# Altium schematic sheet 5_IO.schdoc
size 302 x 215 mm
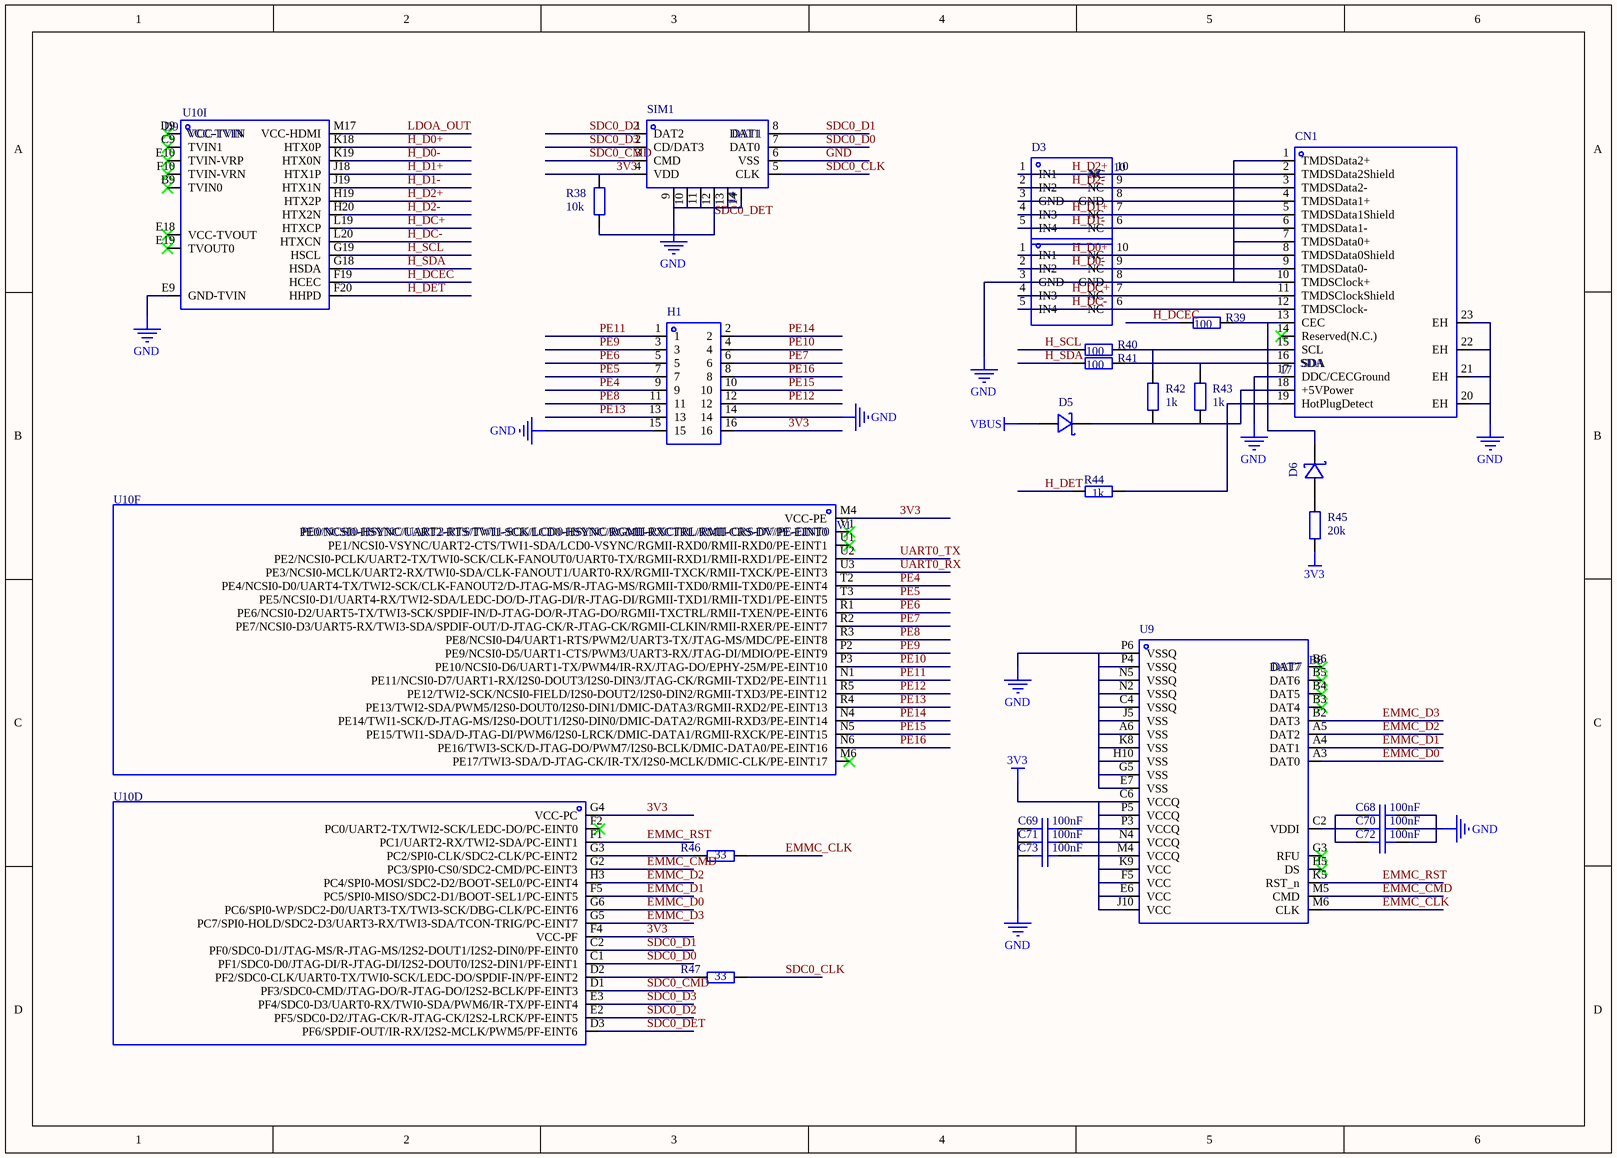
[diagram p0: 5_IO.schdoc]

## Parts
C68  value 100nF
C69  value 100nF
C70  value 100nF
C71  value 100nF
C72  value 100nF
C73  value 100nF
CN1  NUMBER: 17  NAME: SDA  [HDMI-SMD_HD219F-3D05200]
D3  NAME: NC  NUMBER: 10  [SLP2510P8_L2.5-W1.0-P0.50-BL]
D4  (no value)  [SLP2510P8_L2.5-W1.0-P0.50-BL]
D5  (no value)  [SOD-323_L1.8-W1.3-LS2.5-RD]
D6  (no value)  [SOD-323_L1.8-W1.3-LS2.5-RD]
H1  (no value)  [HDR-SMD_16P-P2.54-V-M-R2-C8-S7.4]
R38  value 10k
R39  value 100
R40  value 100
R41  value 100
R42  value 1k
R43  value 1k
R44  value 1k
R45  value 20k
R46  value 33
R47  value 33
SIM1  NAME: DAT1  NUMBER: 14  [SIM-SMD_8P-1040310811]
U9  NAME: DAT7  NUMBER: B6  [FBGA-153_L13.0-W11.5]
U10  (no value)  [ALLWINNER D1]  (parts D,F,I of 10)

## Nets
3V3: C69.1 C71.1 C73.1 H1.16 R38.1 R45.1 SIM1.4(VDD) U9.C6(VCCQ) U9.E6(VCC) U9.F5(VCC) U9.J10(VCC) U9.K9(VCC) U9.M4(VCCQ) U9.N4(VCCQ) U9.P3(VCCQ) U9.P5(VCCQ) U10.F4(VCC-PF) U10.G4(VCC-PC) U10.M4(VCC-PE)
GND: C68.1 C69.2 C70.1 C71.2 C72.1 C73.2 CN1.1(TMDSData2+) CN1.4(TMDSData1+) CN1.7(TMDSData0+) CN1.10(TMDSClock+) CN1.17(DDC/CECGround) CN1.20(EH) CN1.21(EH) CN1.22(EH) CN1.23(EH) D3.3(GND) D3.8(GND) D4.3(GND) D4.8(GND) H1.14 H1.15 SIM1.6(VSS) SIM1.9 SIM1.10 SIM1.11 SIM1.13 SIM1.14 U9.A6(VSS) U9.C4(VSSQ) U9.E7(VSS) U9.G5(VSS) U9.H10(VSS) U9.J5(VSS) U9.K8(VSS) U9.N2(VSSQ) U9.N5(VSSQ) U9.P4(VSSQ) U9.P6(VSSQ) U10.E9(GND-TVIN)
VBUS: D5.2(A)
EMMC_CLK: R46.2 U9.M6(CLK)
EMMC_CMD: U9.M5(CMD) U10.G2(PC3/SPI0-CS0/SDC2-CMD/PC-EINT3)
EMMC_D0: U9.A3(DAT0) U10.G6(PC6/SPI0-WP/SDC2-D0/UART3-TX/TWI3-SCK/DBG-CLK/PC-EINT6)
EMMC_D1: U9.A4(DAT1) U10.F5(PC5/SPI0-MISO/SDC2-D1/BOOT-SEL1/PC-EINT5)
EMMC_D2: U9.A5(DAT2) U10.H3(PC4/SPI0-MOSI/SDC2-D2/BOOT-SEL0/PC-EINT4)
EMMC_D3: U9.B2(DAT3) U10.G5(PC7/SPI0-HOLD/SDC2-D3/UART3-RX/TWI3-SDA/TCON-TRIG/PC-EINT7)
EMMC_RST: U9.K5(RST_n) U10.F1(PC1/UART2-RX/TWI2-SDA/PC-EINT1)
H_D0+: CN1.8(TMDSData0Shield) D4.1(IN1) D4.10(NC) U10.K18(HTX0P)
H_D0-: CN1.9(TMDSData0-) D4.2(IN2) D4.9(NC) U10.K19(HTX0N)
H_D1+: CN1.5(TMDSData1Shield) D3.4(IN3) D3.7(NC) U10.J18(HTX1P)
H_D1-: CN1.6(TMDSData1-) D3.5(IN4) D3.6(NC) U10.J19(HTX1N)
H_D2+: CN1.2(TMDSData2Shield) D3.1(IN1) D3.10(NC) U10.H19(HTX2P)
H_D2-: CN1.3(TMDSData2-) D3.2(IN2) D3.9(NC) U10.H20(HTX2N)
H_DC+: CN1.11(TMDSClockShield) D4.4(IN3) D4.7(NC) U10.L19(HTXCP)
H_DC-: CN1.12(TMDSClock-) D4.5(IN4) D4.6(NC) U10.L20(HTXCN)
H_DCEC: R39.2 U10.F19(HCEC)
H_DET: R44.2 U10.F20(HHPD)
H_SCL: R40.2 U10.G19(HSCL)
H_SDA: R41.2 U10.G18(HSDA)
LDOA_OUT: U10.M17(VCC-HDMI)
PE4: H1.9 U10.T2(PE4/NCSI0-D0/UART4-TX/TWI2-SCK/CLK-FANOUT2/D-JTAG-MS/R-JTAG-MS/RGMII-TXD0/RMII-TXD0/PE-EINT4)
PE5: H1.7 U10.T3(PE5/NCSI0-D1/UART4-RX/TWI2-SDA/LEDC-DO/D-JTAG-DI/R-JTAG-DI/RGMII-TXD1/RMII-TXD1/PE-EINT5)
PE6: H1.5 U10.R1(PE6/NCSI0-D2/UART5-TX/TWI3-SCK/SPDIF-IN/D-JTAG-DO/R-JTAG-DO/RGMII-TXCTRL/RMII-TXEN/PE-EINT6)
PE7: H1.6 U10.R2(PE7/NCSI0-D3/UART5-RX/TWI3-SDA/SPDIF-OUT/D-JTAG-CK/R-JTAG-CK/RGMII-CLKIN/RMII-RXER/PE-EINT7)
PE8: H1.11 U10.R3(PE8/NCSI0-D4/UART1-RTS/PWM2/UART3-TX/JTAG-MS/MDC/PE-EINT8)
PE9: H1.3 U10.P2(PE9/NCSI0-D5/UART1-CTS/PWM3/UART3-RX/JTAG-DI/MDIO/PE-EINT9)
PE10: H1.4 U10.P3(PE10/NCSI0-D6/UART1-TX/PWM4/IR-RX/JTAG-DO/EPHY-25M/PE-EINT10)
PE11: H1.1 U10.N1(PE11/NCSI0-D7/UART1-RX/I2S0-DOUT3/I2S0-DIN3/JTAG-CK/RGMII-TXD2/PE-EINT11)
PE12: H1.12 U10.R5(PE12/TWI2-SCK/NCSI0-FIELD/I2S0-DOUT2/I2S0-DIN2/RGMII-TXD3/PE-EINT12)
PE13: H1.13 U10.R4(PE13/TWI2-SDA/PWM5/I2S0-DOUT0/I2S0-DIN1/DMIC-DATA3/RGMII-RXD2/PE-EINT13)
PE14: H1.2 U10.N4(PE14/TWI1-SCK/D-JTAG-MS/I2S0-DOUT1/I2S0-DIN0/DMIC-DATA2/RGMII-RXD3/PE-EINT14)
PE15: H1.10 U10.N5(PE15/TWI1-SDA/D-JTAG-DI/PWM6/I2S0-LRCK/DMIC-DATA1/RGMII-RXCK/PE-EINT15)
PE16: H1.8 U10.N6(PE16/TWI3-SCK/D-JTAG-DO/PWM7/I2S0-BCLK/DMIC-DATA0/PE-EINT16)
SDC0_CLK: R47.2 SIM1.5(CLK)
SDC0_CMD: SIM1.3(CMD) U10.D1(PF3/SDC0-CMD/JTAG-DO/R-JTAG-DO/I2S2-BCLK/PF-EINT3)
SDC0_D0: SIM1.7(DAT0) U10.C1(PF1/SDC0-D0/JTAG-DI/R-JTAG-DI/I2S2-DOUT0/I2S2-DIN1/PF-EINT1)
SDC0_D1: SIM1.8(DAT1) U10.C2(PF0/SDC0-D1/JTAG-MS/R-JTAG-MS/I2S2-DOUT1/I2S2-DIN0/PF-EINT0)
SDC0_D2: SIM1.1(DAT2) U10.E2(PF5/SDC0-D2/JTAG-CK/R-JTAG-CK/I2S2-LRCK/PF-EINT5)
SDC0_D3: SIM1.2(CD/DAT3) U10.E3(PF4/SDC0-D3/UART0-RX/TWI0-SDA/PWM6/IR-TX/PF-EINT4)
SDC0_DET: R38.2 SIM1.12 U10.D3(PF6/SPDIF-OUT/IR-RX/I2S2-MCLK/PWM5/PF-EINT6)
UART0_RX: U10.U3(PE3/NCSI0-MCLK/UART2-RX/TWI0-SDA/CLK-FANOUT1/UART0-RX/RGMII-TXCK/RMII-TXCK/PE-EINT3)
UART0_TX: U10.U2(PE2/NCSI0-PCLK/UART2-TX/TWI0-SCK/CLK-FANOUT0/UART0-TX/RGMII-RXD1/RMII-RXD1/PE-EINT2)
NetC68_2: C68.2 C70.2 C72.2 U9.C2(VDDI)
NetCN1_13: CN1.13(CEC) D6.1(C) R39.1
NetCN1_15: CN1.15(SCL) R40.1 R42.2
NetCN1_16: CN1.16(SDA) R41.1 R43.2
NetCN1_18: CN1.18(+5VPower) D5.1(C) R42.1 R43.1
NetCN1_19: CN1.19(HotPlugDetect) R44.1
NetD6_2: D6.2(A) R45.2
NetR46_1: R46.1 U10.G3(PC2/SPI0-CLK/SDC2-CLK/PC-EINT2)
NetR47_1: R47.1 U10.D2(PF2/SDC0-CLK/UART0-TX/TWI0-SCK/LEDC-DO/SPDIF-IN/PF-EINT2)

Not connected (* = marked no-connect by the designer): CN1 14(Reserved(N.C.))*; U9 B3(DAT4)* B4(DAT5)* B5(DAT6)* B6(DAT7)* G3(RFU)* H5(DS)*; U10 B9(TVIN0)* C9(TVIN1)* D9(VCC-TVIN)* E10(TVIN-VRP)* E18(VCC-TVOUT)* E19(TVOUT0)* F2(PC0/UART2-TX/TWI2-SCK/LEDC-DO/PC-EINT0)* F10(TVIN-VRN)* M6(PE17/TWI3-SDA/D-JTAG-CK/IR-TX/I2S0-MCLK/DMIC-CLK/PE-EINT17)* U1(PE1/NCSI0-VSYNC/UART2-CTS/TWI1-SDA/LCD0-VSYNC/RGMII-RXD0/RMII-RXD0/PE-EINT1)* V1(PE0/NCSI0-HSYNC/UART2-RTS/TWI1-SCK/LCD0-HSYNC/RGMII-RXCTRL/RMII-CRS-DV/PE-EINT0)*

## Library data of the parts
C68-C73 = FN15X104K250PNG: Manufacturer: PSA(信昌电陶); Add into BOM: yes; Tolerance: ±10%; Voltage Rated: 25V; Temperature Coefficient: X7R; Description: 容值:100nF;精度:±10%;额定电压:25V;温度系数:X7R;; NAME: 1; Pin Type: IN
CN1 = HD219F-3D05200: Manufacturer: ATOM(爱特姆); Add into BOM: yes; Connector Type: HDMI; Gender: 母; Current Rating (Max): 500mA; Description: 连接器类型:HDMI;公母:母;总PIN位数:19;排数:-;安装方式:卧贴;额定电流:500mA;工作温度范围:-25~+85;
D3 D4 = RClamp0524PATCT: Manufacturer: SEMTECH; Add into BOM: yes; Description: VBR=6V， Vc=15V ，Ipp=5A
D5 D6 = 1N5819WS: Manufacturer: PJSEMI(平晶微); Symbol: 1N5819WS_C440261; Add into BOM: yes; Reverse Voltage (Vr): 40V; Average Rectified Current (Io): 1A; Forward Voltage (Vf@If): 900mV@3A; Description: 直流反向耐压(Vr):40V;平均整流电流(Io):1A;正向压降(Vf):900mV@3A;; NAME: C; NUMBER: 1; Pin Type: IN
H1 = X6521WVS-2x08H-C60D74: Manufacturer: XKB Connectivity(中国星坤); Add into BOM: yes; Pitch: 2.54mm; Pin Structure: 2x8P; Circluar Pins/Square Pins: 方针; Current Rating (Max): 3A; Voltage Rating (Max): 250V; Description: 间距:2.54mm;总PIN位数:16;排数:2;插针结构:2x8P;行距:-;安装类型:立贴;圆针/方针:方针;额定电流:3A;额定电压:250V;配合针长度:6mm;塑高:2.5mm;端接针长度:-;工作温度范围:-40~+105;
R38-R47 = TR0402D10K0Q1025Z_1: Manufacturer: EVER OHMS(天二科技); Symbol: TR0402D10KQ1025_1; Add into BOM: yes; Tolerance: ±0.5%; Power(Watts): 63mW; Temperature Coefficient: ±25ppm/; Overload Voltage (Max): 25V; Description: 电阻类型:薄膜电阻;阻值:10k;精度:±0.5%;功率:63mW;温度系数:±25ppm/;最大工作电压:25V;工作温度范围:-55~+155;
SIM1 = 1040310811: Manufacturer: MOLEX; Add into BOM: yes; Card Connection Mode: 拔插式; Card Type: MicroSD卡(TF卡); Connector Type: 卡座; Maximum Body Height: 1.42mm; Description: 卡连接方式:拔插式;卡类型:MicroSD卡(TF卡);连接器类型:卡座;本体最大高度:1.42mm;工作温度范围:-;
U9 = EMMC BGA153: Manufacturer: Kingston(金士顿); Manufacturer Part: EMMC04G-M627-A01; Pin Type: IN; Add into BOM: yes
U10 = Allwinner D1-H: Pin Type: IN; Add into BOM: yes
